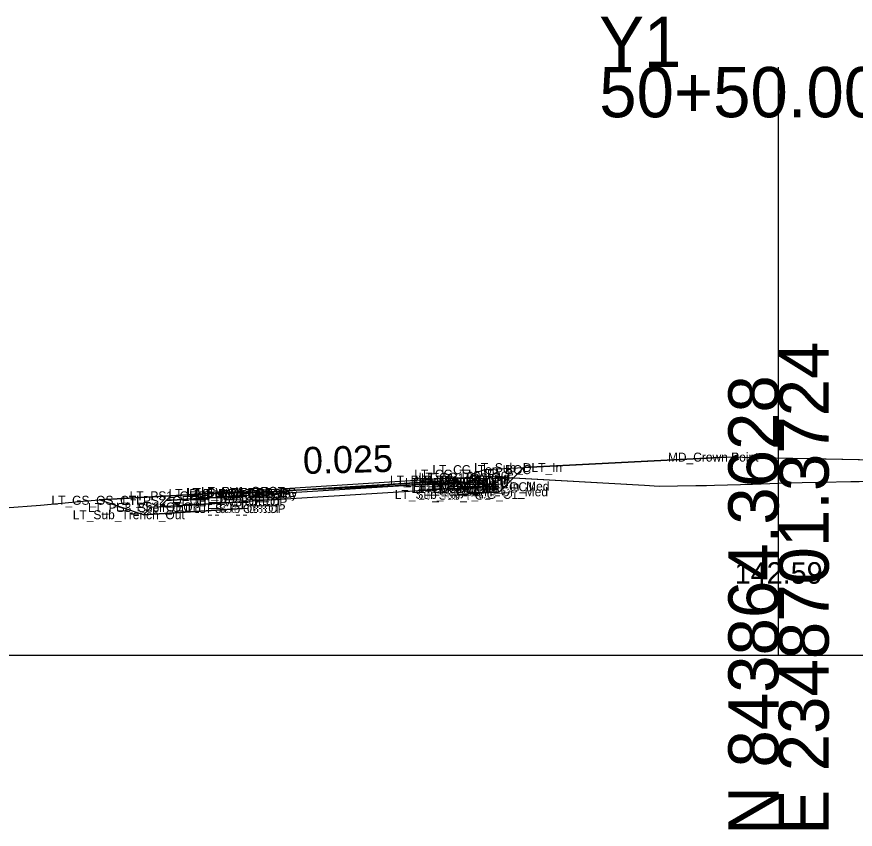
# Model space of a CAD drawing. Extents: x -26 to 2349090, y -10 to 844481.
# Drawn here: x 1107.53 to 1154.27, y 15990.31 to 16035.59 of the extents above; entities that cross this region are included whole.
import ezdxf

# ---------------------------------------------------------------- set-up
doc = ezdxf.new("R2010")
doc.units = 0
for name, color, linetype in [('Exist CMT Pavement', 7, 'Continuous'), ('Exist Cross Section Cell', 7, 'Continuous'), ('Exist XS Center Line Elevation Label', 7, 'Continuous'), ('Exist XS Ground Line', 7, 'Continuous'), ('Prop CMT Conc Surface', 7, 'Continuous'), ('Prop CMT Concrete Structures', 7, 'Continuous'), ('Prop CMT Pvmt Course 1', 7, 'Continuous'), ('Prop CMT Pvmt Course 1 CG', 7, 'Continuous'), ('Prop CMT Pvmt Course 1 Wedge', 7, 'Continuous'), ('Prop CMT Pvmt Course 2', 7, 'Continuous'), ('Prop CMT Pvmt Course 2 Wedge', 7, 'Continuous'), ('Prop CMT Pvmt Course 3', 7, 'Continuous'), ('Prop CMT Pvmt Surface', 7, 'Continuous'), ('Prop CMT Pvmt Surface Shoulder', 7, 'Continuous'), ('Prop CMT Pvmt Wedge Surface 1', 7, 'Continuous'), ('Prop CMT Pvmt Wedge Surface 2', 7, 'Continuous'), ('Prop CMT Pvmt Wedge Surface 3', 7, 'Continuous'), ('Prop CMT Shld Paved Course 1', 7, 'Continuous'), ('Prop CMT Shld Paved Course 2', 7, 'Continuous'), ('Prop CMT Shld Paved Course 3', 7, 'Continuous'), ('Prop CMT Slope Grass', 7, 'Continuous'), ('Prop CMT Subgrade Earthwork', 7, 'Continuous'), ('Prop XS Earthwork Shape', 7, 'Continuous'), ('Prop XS SE Text', 7, 'Continuous'), ('Scratch_Level_0', 7, 'Continuous')]:
    doc.layers.add(name, color=color, linetype=linetype)

msp = doc.modelspace()

# ---------------------------------------------------------------- linework, layer by layer
at = {"layer": 'Exist CMT Pavement'}
for p, q in [((1129.209, 16009.478), (1129.678, 16009.501)), ((1129.678, 16009.501), (1131.77, 16009.601)), ((1131.77, 16009.601), (1132.12, 16009.624)), ((1120.123, 16009.073), (1120.938, 16009.108)), ((1120.938, 16009.108), (1121.508, 16009.133)), ((1121.508, 16009.133), (1122.731, 16009.189)), ((1122.731, 16009.189), (1123.409, 16009.221)), ((1123.409, 16009.221), (1123.731, 16009.235)), ((1123.731, 16009.235), (1125.281, 16009.304)), ((1125.281, 16009.304), (1126.469, 16009.354)), ((1126.469, 16009.354), (1128.628, 16009.451)), ((1128.628, 16009.451), (1129.209, 16009.478))]:
    msp.add_line(p, q, dxfattribs=at)
at = {"layer": 'Exist Cross Section Cell'}
for p, q in [((1150, 16000), (1150, 16032.786)), ((1000, 16000), (1150, 16000)), ((1150, 16000), (1300, 16000))]:
    msp.add_line(p, q, dxfattribs=at)
at = {"layer": 'Exist XS Ground Line'}
msp.add_lwpolyline([(1106.856, 16008.215), (1108.856, 16008.373), (1111.004, 16008.565), (1112.125, 16008.663), (1112.72, 16008.7), (1115.227, 16008.854), (1115.646, 16008.881), (1116.751, 16008.921), (1117.22, 16008.951), (1118.22, 16008.993), (1119.614, 16009.051), (1120.938, 16009.108), (1121.508, 16009.133), (1122.731, 16009.189), (1123.409, 16009.221), (1123.731, 16009.235), (1125.281, 16009.304), (1126.469, 16009.354), (1128.628, 16009.451), (1129.209, 16009.478), (1129.678, 16009.501), (1131.77, 16009.601), (1132.4, 16009.643), (1132.793, 16009.674), (1133.267, 16009.998), (1142.531, 16009.474), (1143.347, 16009.428), (1145.38, 16009.462), (1145.986, 16009.46), (1146.428, 16009.474), (1147.873, 16009.518), (1148.553, 16009.542), (1150, 16009.59), (1151.308, 16009.625), (1152.404, 16009.646), (1154.035, 16009.68), (1154.498, 16009.694)], dxfattribs=at)
at = {"layer": 'Prop CMT Conc Surface'}
for p, q in [((1132.872, 16009.93), (1132.873, 16010.097)), ((1132.873, 16010.097), (1133.632, 16010.347)), ((1132.122, 16009.884), (1132.872, 16009.93))]:
    msp.add_line(p, q, dxfattribs=at)
at = {"layer": 'Prop CMT Concrete Structures'}
for p, q in [((1132.872, 16009.93), (1132.873, 16010.097)), ((1132.873, 16010.097), (1133.632, 16010.347)), ((1133.632, 16010.347), (1133.632, 16009.394)), ((1132.122, 16009.884), (1132.872, 16009.93)), ((1132.122, 16009.3), (1132.122, 16009.884)), ((1133.632, 16009.394), (1132.122, 16009.3))]:
    msp.add_line(p, q, dxfattribs=at)
at = {"layer": 'Prop CMT Pvmt Course 1'}
for p, q in [((1132.122, 16009.884), (1120.121, 16009.137)), ((1120.121, 16009.012), (1132.122, 16009.759)), ((1132.122, 16009.634), (1132.122, 16009.884)), ((1132.122, 16009.759), (1132.122, 16009.634)), ((1132.122, 16009.634), (1132.122, 16009.634)), ((1120.121, 16009.137), (1120.121, 16008.887)), ((1120.121, 16008.887), (1120.121, 16009.012)), ((1120.121, 16008.887), (1120.121, 16008.887))]:
    msp.add_line(p, q, dxfattribs=at)
at = {"layer": 'Prop CMT Pvmt Course 1 CG'}
for p, q in [((1132.122, 16009.3), (1134.132, 16009.425)), ((1132.122, 16008.967), (1132.122, 16009.3)), ((1134.446, 16009.112), (1132.122, 16008.967)), ((1134.132, 16009.425), (1134.446, 16009.112))]:
    msp.add_line(p, q, dxfattribs=at)
at = {"layer": 'Prop CMT Pvmt Course 1 Wedge'}
for p, q in [((1126.469, 16009.407), (1128.628, 16009.541)), ((1128.628, 16009.541), (1129.209, 16009.577)), ((1129.209, 16009.577), (1129.678, 16009.607)), ((1129.678, 16009.501), (1129.209, 16009.478)), ((1129.678, 16009.607), (1131.77, 16009.737)), ((1131.014, 16009.565), (1129.678, 16009.501)), ((1131.77, 16009.612), (1131.014, 16009.565)), ((1131.77, 16009.737), (1132.122, 16009.759)), ((1132.122, 16009.634), (1131.77, 16009.612)), ((1132.122, 16009.759), (1132.122, 16009.634)), ((1123.638, 16009.231), (1123.731, 16009.236)), ((1123.731, 16009.235), (1123.638, 16009.231)), ((1123.731, 16009.236), (1125.281, 16009.333)), ((1125.281, 16009.304), (1123.731, 16009.235)), ((1125.281, 16009.333), (1126.469, 16009.407)), ((1126.469, 16009.354), (1125.281, 16009.304)), ((1128.628, 16009.451), (1126.469, 16009.354)), ((1129.209, 16009.478), (1128.628, 16009.451))]:
    msp.add_line(p, q, dxfattribs=at)
at = {"layer": 'Prop CMT Pvmt Course 2'}
for p, q in [((1120.121, 16008.553), (1120.121, 16008.887)), ((1120.121, 16008.887), (1120.121, 16008.887)), ((1120.121, 16008.887), (1120.121, 16008.553)), ((1120.121, 16008.553), (1120.121, 16008.553))]:
    msp.add_line(p, q, dxfattribs=at)
at = {"layer": 'Prop CMT Pvmt Course 2 Wedge'}
for p, q in [((1131.014, 16009.565), (1131.77, 16009.612)), ((1131.77, 16009.601), (1131.014, 16009.565)), ((1131.77, 16009.612), (1132.122, 16009.634)), ((1132.122, 16009.624), (1131.77, 16009.601)), ((1132.122, 16009.634), (1132.122, 16009.624))]:
    msp.add_line(p, q, dxfattribs=at)
at = {"layer": 'Prop CMT Pvmt Course 3'}
for p, q in [((1120.121, 16008.553), (1120.121, 16008.553)), ((1120.121, 16008.553), (1120.121, 16008.178)), ((1120.121, 16008.178), (1120.121, 16008.553)), ((1120.121, 16008.178), (1120.121, 16008.178))]:
    msp.add_line(p, q, dxfattribs=at)
at = {"layer": 'Prop CMT Pvmt Surface'}
msp.add_line((1132.122, 16009.884), (1120.121, 16009.137), dxfattribs=at)
at = {"layer": 'Prop CMT Pvmt Surface Shoulder'}
msp.add_line((1120.121, 16009.137), (1116.121, 16008.888), dxfattribs=at)
at = {"layer": 'Prop CMT Pvmt Wedge Surface 1'}
for p, q in [((1132.122, 16009.759), (1120.121, 16009.012)), ((1132.122, 16009.884), (1132.122, 16009.759)), ((1132.122, 16009.759), (1132.122, 16009.759)), ((1120.121, 16009.012), (1120.121, 16009.137)), ((1120.121, 16009.012), (1120.121, 16009.012))]:
    msp.add_line(p, q, dxfattribs=at)
at = {"layer": 'Prop CMT Pvmt Wedge Surface 2'}
for p, q in [((1132.122, 16009.634), (1120.121, 16008.887)), ((1132.122, 16009.884), (1132.122, 16009.634)), ((1120.121, 16008.887), (1120.121, 16009.137))]:
    msp.add_line(p, q, dxfattribs=at)
at = {"layer": 'Prop CMT Pvmt Wedge Surface 3'}
for p, q in [((1132.122, 16009.884), (1132.122, 16009.3)), ((1132.122, 16009.3), (1120.121, 16008.553)), ((1120.121, 16008.553), (1120.121, 16009.137))]:
    msp.add_line(p, q, dxfattribs=at)
at = {"layer": 'Prop CMT Shld Paved Course 1'}
for p, q in [((1120.121, 16009.137), (1116.121, 16008.888)), ((1120.121, 16008.887), (1120.121, 16009.137)), ((1116.121, 16008.888), (1115.855, 16008.621)), ((1115.855, 16008.621), (1120.121, 16008.887))]:
    msp.add_line(p, q, dxfattribs=at)
at = {"layer": 'Prop CMT Shld Paved Course 2'}
for p, q in [((1115.855, 16008.621), (1115.499, 16008.266)), ((1115.499, 16008.266), (1120.121, 16008.553)), ((1120.121, 16008.887), (1115.855, 16008.621)), ((1120.121, 16008.553), (1120.121, 16008.887))]:
    msp.add_line(p, q, dxfattribs=at)
at = {"layer": 'Prop CMT Shld Paved Course 3'}
for p, q in [((1120.121, 16008.553), (1115.499, 16008.266)), ((1120.121, 16008.178), (1120.121, 16008.553)), ((1114.999, 16008.235), (1114.599, 16007.835)), ((1114.599, 16007.835), (1120.121, 16008.178)), ((1115.499, 16008.266), (1114.999, 16008.235))]:
    msp.add_line(p, q, dxfattribs=at)
at = {"layer": 'Prop CMT Slope Grass'}
for p, q in [((1133.632, 16010.347), (1147.061, 16011.046)), ((1160.49, 16010.777), (1147.061, 16011.046)), ((1116.121, 16008.888), (1112.125, 16008.663))]:
    msp.add_line(p, q, dxfattribs=at)
at = {"layer": 'Prop CMT Subgrade Earthwork'}
for p, q in [((1135.793, 16010.459), (1134.446, 16009.112)), ((1132.122, 16009.624), (1132.122, 16008.967)), ((1120.121, 16008.178), (1120.123, 16009.073)), ((1132.122, 16008.967), (1134.446, 16009.112)), ((1114.599, 16007.835), (1112.125, 16008.663)), ((1120.121, 16008.178), (1114.599, 16007.835)), ((1120.121, 16008.178), (1120.121, 16008.178))]:
    msp.add_line(p, q, dxfattribs=at)
at = {"layer": 'Prop XS Earthwork Shape'}
for points in [[(1147.873, 16009.518), (1148.553, 16009.542), (1150, 16009.59), (1151.308, 16009.625), (1152.404, 16009.646), (1154.035, 16009.68), (1154.498, 16009.694), (1155.385, 16009.722), (1156.813, 16009.778), (1158.265, 16009.841), (1159.135, 16009.879), (1159.183, 16009.881), (1158.242, 16010.822), (1147.061, 16011.046), (1135.793, 16010.459), (1135.221, 16009.887), (1142.531, 16009.474), (1143.347, 16009.428), (1145.38, 16009.462), (1145.986, 16009.46), (1146.428, 16009.474)], [(1132.4, 16009.643), (1132.793, 16009.674), (1133.267, 16009.998), (1135.221, 16009.887), (1134.446, 16009.112), (1132.122, 16008.967), (1132.12, 16009.624)], [(1117.22, 16008.951), (1118.22, 16008.993), (1119.614, 16009.051), (1120.123, 16009.073), (1120.121, 16008.178), (1114.599, 16007.835), (1112.125, 16008.663), (1116.121, 16008.888), (1116.524, 16008.913), (1116.751, 16008.921)], [(1115.227, 16008.854), (1115.646, 16008.881), (1116.524, 16008.913), (1116.121, 16008.888), (1112.125, 16008.663), (1112.72, 16008.7)]]:
    msp.add_lwpolyline(points, close=True, dxfattribs=at)

# ---------------------------------------------------------------- texts
at = {"layer": 'Exist Cross Section Cell'}
for s, p in [('Y1', (1140, 16032.786)), ('50+50.00 / 1', (1140, 16029.986))]:
    msp.add_text(s, height=2.8, dxfattribs=at).set_placement(p)
for s, p in [('E 2348701.3724', (1152.8, 15990)), ('N 843864.3628', (1150, 15990))]:
    msp.add_text(s, height=2.8, rotation=90, dxfattribs=at).set_placement(p)
at = {"layer": 'Exist XS Center Line Elevation Label'}
msp.add_text('142.59', height=1.2, dxfattribs=at).set_placement((1147.553, 16003.99))
at = {"layer": 'Prop XS SE Text'}
msp.add_text('0.025', height=1.5, rotation=1.4321, dxfattribs=at).set_placement((1123.502, 16010.104))
at = {"layer": 'Scratch_Level_0'}
for s, p in [('MD_Crown Point', (1143.829, 16010.796)), ('LT_CG_Top_BOC', (1130.703, 16010.097)), ('LT_Sub_DLT_In', (1133.03, 16010.209)), ('LT_PV1_Overlay_Null', (1128.338, 16009.509)), ('LT_CG_Top_Face', (1129.688, 16009.847)), ('LT_PV1_IEEOP', (1129.752, 16009.509)), ('LT_CG_Top_Gut', (1129.931, 16009.68)), ('LT_PV1_PGL', (1130.067, 16009.634)), ('LT_PV_IEEOP_EG', (1129.168, 16009.374)), ('LT_CG_Bot_IE1', (1129.527, 16009.05)), ('LT_PV2_IEEOP', (1129.61, 16009.384)), ('LT_PV3_IEEOP', (1129.61, 16009.05)), ('LT_PV2_PGL', (1129.925, 16009.384)), ('LT_PV3_PGL', (1129.925, 16009.05)), ('LT_CG1_Shelf_In_Med', (1130.203, 16009.175)), ('LT_CG_Bot_BOC1', (1130.628, 16009.144)), ('LT_PS1_OEOP', (1113.822, 16008.638)), ('LT_PV1_OEOT Overlay', (1115.991, 16008.762)), ('LT_Sub Tie Out', (1116.957, 16008.823)), ('LT_PV_OEEOP_EG', (1117.008, 16008.823)), ('LT_PV2_OEEOP', (1117.448, 16008.637)), ('LT_PV1_OEEOP', (1117.59, 16008.762)), ('LT_PV2_OEOT', (1117.664, 16008.637)), ('LT_PV1_OEOT', (1117.806, 16008.887)), ('LT_Sub_IEOT_CG_C1', (1128.602, 16008.717)), ('LT_Sub_PGL', (1129.901, 16008.675)), ('LT_Sub_IEOP_Med', (1131.162, 16008.862)), ('LT_GS_OS_CTL', (1109.464, 16008.389)), ('LT_PS2_OEOP', (1113.414, 16008.371)), ('LT_PV3_OEEOP', (1117.448, 16008.303)), ('LT_PV3_OEOT', (1117.664, 16008.303)), ('LT_Sub_Trench_Out', (1110.65, 16007.585)), ('LT_PS3_Shelf_Out', (1111.495, 16007.985)), ('LT_PS3_OEOP', (1113.058, 16008.016)), ('LT_Sub_OEEOP', (1117.424, 16007.928)), ('LT_Sub_OEOT', (1117.641, 16007.928))]:
    msp.add_text(s, height=0.5, dxfattribs=at).set_placement(p)

doc.saveas('drawing.dxf')
